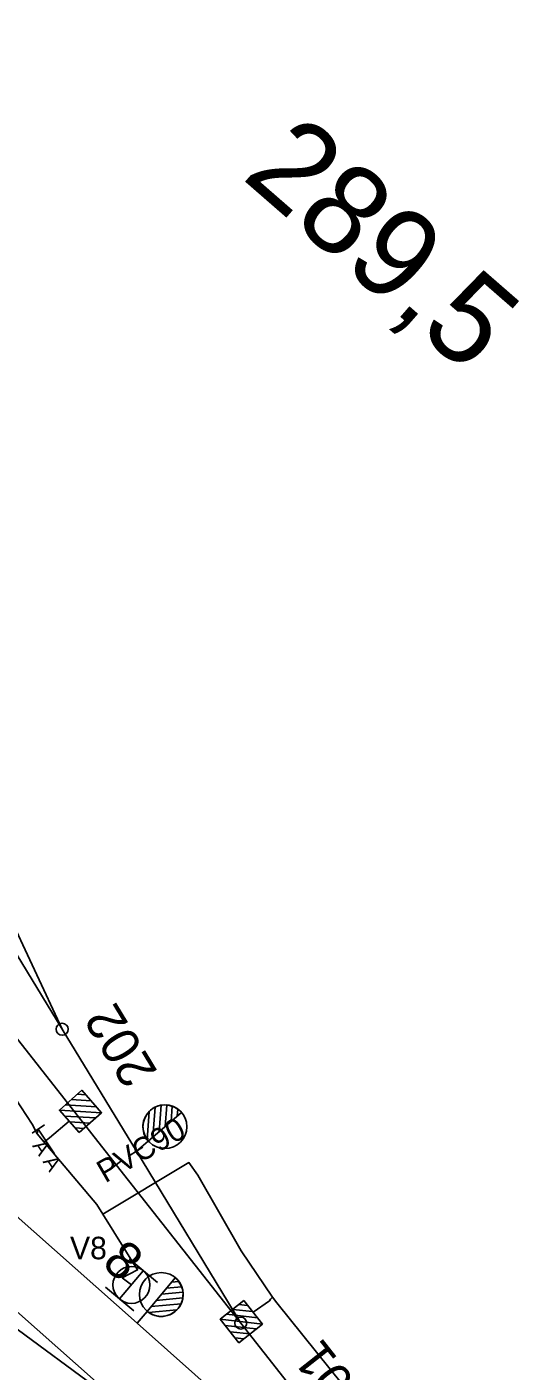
# Model space of a CAD drawing. Extents: x -496570 to -495506, y -1089156 to -1088046.
# Drawn here: x -495866 to -495833.1, y -1088709.5 to -1088619.8 of the extents above; entities that cross this region are included whole.
import ezdxf

# ---------------------------------------------------------------- set-up
doc = ezdxf.new("R2010")
doc.units = 0
for name, color, linetype in [('11', 7, 'Continuous'), ('14', 7, 'Continuous'), ('15', 7, 'Continuous'), ('20', 7, 'Continuous'), ('27', 7, 'Continuous'), ('54', 7, 'Continuous'), ('PŮVODNÍ_NÁVRH', 7, 'Continuous')]:
    doc.layers.add(name, color=color, linetype=linetype)

msp = doc.modelspace()

# ---------------------------------------------------------------- linework, layer by layer
at = {"layer": '14'}
msp.add_line((-495858.601, -1088706.274), (-495844.395, -1088718.899), dxfattribs=at)
for points in [[(-495842.928, -1088717.493), (-495843.661, -1088716.477), (-495851.703, -1088706.254), (-495860.009, -1088695.696), (-495879.111, -1088671.4), (-495889.727, -1088657.952), (-495895.948, -1088650.027), (-495908.172, -1088634.454), (-495920.247, -1088619.061), (-495937.589, -1088596.936)], [(-495863.612, -1088686.663), (-495871.01, -1088670.829), (-495876.153, -1088659.315), (-495885.306, -1088638.927), (-495892.793, -1088622.727)], [(-495851.703, -1088706.254), (-495858.66, -1088694.79), (-495863.612, -1088686.663), (-495872.713, -1088671.728)]]:
    msp.add_lwpolyline(points, dxfattribs=at)
at = {"layer": '15'}
for p, q in [((-495861.329, -1088691.83), (-495863.404, -1088691.699)), ((-495861.68, -1088691.432), (-495863.005, -1088691.348)), ((-495862.03, -1088691.034), (-495862.607, -1088690.998)), ((-495860.978, -1088692.228), (-495863.801, -1088692.05)), ((-495861.376, -1088692.578), (-495863.451, -1088692.447)), ((-495861.774, -1088692.929), (-495863.1, -1088692.846)), ((-495862.172, -1088693.28), (-495862.749, -1088693.243)), ((-495857.255, -1088703.558), (-495859.142, -1088701.973)), ((-495858.199, -1088702.766), (-495859.783, -1088704.652)), ((-495858.84, -1088705.445), (-495860.727, -1088703.86)), ((-495851.823, -1088705.013), (-495851.248, -1088705.078)), ((-495853.067, -1088706.004), (-495850.257, -1088706.322)), ((-495852.653, -1088705.674), (-495850.587, -1088705.908)), ((-495852.238, -1088705.343), (-495850.918, -1088705.492)), ((-495852.737, -1088706.419), (-495850.671, -1088706.652)), ((-495852.406, -1088706.834), (-495851.087, -1088706.983)), ((-495852.076, -1088707.249), (-495851.501, -1088707.314))]:
    msp.add_line(p, q, dxfattribs=at)
for points in [[(-495862.479, -1088693.55), (-495863.801, -1088692.05), (-495862.301, -1088690.727), (-495860.978, -1088692.228)], [(-495862.479, -1088693.55), (-495863.801, -1088692.05), (-495862.301, -1088690.727), (-495860.978, -1088692.228)], [(-495851.503, -1088704.758), (-495850.257, -1088706.322), (-495851.821, -1088707.568), (-495853.067, -1088706.004)], [(-495851.503, -1088704.758), (-495850.257, -1088706.322), (-495851.821, -1088707.568), (-495853.067, -1088706.004)]]:
    msp.add_lwpolyline(points, close=True, dxfattribs=at)
for points in [[(-495862.479, -1088693.55), (-495863.801, -1088692.05), (-495862.301, -1088690.727), (-495860.978, -1088692.228), (-495862.479, -1088693.55)], [(-495862.479, -1088693.55), (-495863.801, -1088692.05), (-495862.301, -1088690.727), (-495860.978, -1088692.228), (-495862.479, -1088693.55)], [(-495851.503, -1088704.758), (-495850.257, -1088706.322), (-495851.821, -1088707.568), (-495853.067, -1088706.004), (-495851.503, -1088704.758)], [(-495851.503, -1088704.758), (-495850.257, -1088706.322), (-495851.821, -1088707.568), (-495853.067, -1088706.004), (-495851.503, -1088704.758)]]:
    msp.add_lwpolyline(points, dxfattribs=at)
msp.add_circle((-495858.993, -1088703.714), 1.232, dxfattribs=at)
at = {"layer": '20'}
for p, q in [((-495864.787, -1088693.04), (-495865.621, -1088693.59)), ((-495864.114, -1088694.968), (-495865.204, -1088693.315))]:
    msp.add_line(p, q, dxfattribs=at)
at = {"layer": '27'}
for p, q in [((-495857.152, -1088693.501), (-495857.015, -1088691.73)), ((-495856.75, -1088693.154), (-495856.639, -1088691.714)), ((-495857.944, -1088694.031), (-495857.799, -1088692.138)), ((-495857.877, -1088694.123), (-495855.655, -1088692.217)), ((-495855.655, -1088692.217), (-495857.877, -1088694.122)), ((-495857.554, -1088693.846), (-495857.401, -1088691.854)), ((-495856.347, -1088692.81), (-495856.269, -1088691.798)), ((-495855.944, -1088692.464), (-495855.907, -1088691.989)), ((-495857.878, -1088694.123), (-495858.66, -1088694.79)), ((-495857.877, -1088694.122), (-495857.877, -1088694.123)), ((-495859.087, -1088695.049), (-495858.233, -1088694.531)), ((-495860.401, -1088696.005), (-495859.617, -1088695.387)), ((-495858.985, -1088712.277), (-495875.095, -1088700.424)), ((-495857.945, -1088705.481), (-495856.073, -1088703.231)), ((-495856.073, -1088703.231), (-495857.945, -1088705.482)), ((-495856.994, -1088704.339), (-495855.556, -1088704.207)), ((-495856.655, -1088703.932), (-495855.644, -1088703.839)), ((-495856.316, -1088703.523), (-495855.841, -1088703.48)), ((-495857.674, -1088705.154), (-495855.684, -1088704.971)), ((-495857.335, -1088704.747), (-495855.566, -1088704.584)), ((-495857.946, -1088705.482), (-495858.601, -1088706.274)), ((-495857.945, -1088705.482), (-495857.945, -1088705.481)), ((-495857.853, -1088705.547), (-495855.963, -1088705.374))]:
    msp.add_line(p, q, dxfattribs=at)
for points in [[(-495863.612, -1088686.663), (-495871.01, -1088670.829)], [(-495858.66, -1088694.79), (-495863.612, -1088686.663), (-495872.713, -1088671.728)], [(-495858.601, -1088706.274), (-495871.032, -1088695.249), (-495883.36, -1088684.314)], [(-495851.703, -1088706.254), (-495858.66, -1088694.79)], [(-495842.928, -1088717.493), (-495843.661, -1088716.477), (-495851.703, -1088706.254), (-495860.009, -1088695.696)], [(-495873.948, -1088699.018), (-495858.985, -1088712.277), (-495848.789, -1088721.31)]]:
    msp.add_lwpolyline(points, dxfattribs=at)
for centre, radius in [((-495863.612, -1088686.663), 0.4), ((-495856.761, -1088693.163), 1.462), ((-495857.003, -1088704.351), 1.462), ((-495851.703, -1088706.254), 0.4)]:
    msp.add_circle(centre, radius, dxfattribs=at)
for centre, start, end in [((-495856.766, -1088693.17), 40.62641, 220.58726), ((-495857.009, -1088704.356), 230.26886, 50.22971)]:
    msp.add_arc(centre, 1.464, start, end, dxfattribs=at)
at = {"layer": '54'}
msp.add_line((-495865.28, -1088693.642), (-495865.204, -1088693.315), dxfattribs=at)
for points in [[(-495866.758, -1088691.249), (-495865.624, -1088692.99), (-495865.28, -1088693.642), (-495864.81, -1088694.196), (-495861.29, -1088698.346), (-495860.894, -1088698.999), (-495855.16, -1088695.55), (-495854.56, -1088696.39), (-495851.68, -1088701.44), (-495849.58, -1088704.52), (-495849.29, -1088704.91), (-495844.91, -1088710.36)], [(-495863.14, -1088692.8), (-495864.46, -1088693.91), (-495864.55, -1088693.97), (-495864.81, -1088694.196)], [(-495860.894, -1088698.999), (-495858.581, -1088702.707), (-495859.61, -1088703.23), (-495858.991, -1088703.709)], [(-495849.58, -1088704.52), (-495849.71, -1088704.67), (-495849.78, -1088704.77), (-495850.88, -1088705.54)]]:
    msp.add_lwpolyline(points, dxfattribs=at)
at = {"layer": 'PŮVODNÍ_NÁVRH'}
msp.add_line((-495860.894, -1088698.999), (-495855.16, -1088695.55), dxfattribs=at)

# ---------------------------------------------------------------- texts
at = {"layer": '11'}
msp.add_text('289,5', height=6, rotation=318.94379, dxfattribs=at).set_placement((-495851.716, -1088629.863))
at = {"layer": '15'}
msp.add_text('V8', height=1.5, dxfattribs=at).set_placement((-495863.087, -1088702.002))
at = {"layer": '20'}
msp.add_text('  A A', height=1, rotation=303.38851, dxfattribs=at).set_placement((-495866.041, -1088693.815))
at = {"layer": '27'}
for s, rotation, p in [('202', 121.25175, (-495857.206, -1088689.502)), ('8', 317.44522, (-495861.043, -1088702.361)), ('201', 128.19063, (-495842.868, -1088711.586))]:
    msp.add_text(s, height=2.5, rotation=rotation, dxfattribs=at).set_placement(p)
at = {"layer": '54'}
msp.add_text('PVC90', height=1.5, rotation=30.05097, dxfattribs=at).set_placement((-495860.737, -1088696.947))

doc.saveas('drawing.dxf')
